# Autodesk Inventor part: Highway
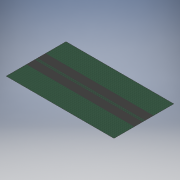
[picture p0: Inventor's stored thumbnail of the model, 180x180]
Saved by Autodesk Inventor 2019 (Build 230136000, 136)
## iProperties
Created: 2018-12
Part Number: Highway
Material: Generic
Document SubType Name: Modeling
Designer: Patel Family
Density: 1 g/cm^3
Appearance: Green Polished
Author: Patel Family
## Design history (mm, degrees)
sketch "Sketch1"
  geometry: L1 (-1703.23, 945.159)-(1703.23, 945.159); L2 (1703.23, 945.159)-(1703.23, -945.159); L3 (1703.23, -945.159)-(-1703.23, -945.159); L4 (-1703.23, -945.159)-(-1703.23, 945.159); L5 (-1703.23, 945.159)-(1703.23, -945.159); L6 (1703.23, 945.159)-(-1703.23, -945.159); 1 further point
  constraints: 12 end point, 2 midpoint, 2 parallel, 1 horizontal, 1 perpendicular
  dimensions: "d8" = 1890.31814 distance between parallel lines of L1 L3
extrude "Extrusion1" new body sketch "Sketch1" distance "d0" = 0.2; taper "d1" = 0 deg
sketch "Sketch2"
  geometry: L1 (1703.23, -945.159)-(1703.23, 945.159) reference; L2 (-1703.23, -44.963)-(1703.23, -44.963); L3 (1703.23, -44.963)-(1703.23, 44.963); L4 (1703.23, 44.963)-(-1703.23, 44.963); L5 (-1703.23, 44.963)-(-1703.23, -44.963); L6 (-1703.23, -44.963)-(1703.23, 44.963); L7 (1703.23, -44.963)-(-1703.23, 44.963); L8 (1703.23, -44.963)-(-1703.23, -44.963); L9 (-1703.23, -44.963)-(-1703.23, 44.963); L10 (-1703.23, 44.963)-(1703.23, 44.963); L11 (1703.23, 44.963)-(1703.23, -44.963); L12 (1703.23, -44.963)-(-1703.23, 44.963); L13 (-1703.23, -44.963)-(1703.23, 44.963); 1 further point
  constraints: 24 end point, 4 midpoint, 4 parallel, 2 horizontal, 2 perpendicular, 1 point on line
  dimensions: "d9" = 89.92631 distance between parallel lines of L2 L4
extrude "Extrusion2" join sketch "Sketch2" distance "d2" = 0.0002; taper "d3" = 0 deg
sketch "Sketch3"
  geometry: L1 (-1705.81, -296.952)-(1705.81, -296.952); L2 (1705.81, -296.952)-(1705.81, 296.952); L3 (1705.81, 296.952)-(-1705.81, 296.952); L4 (-1705.81, 296.952)-(-1705.81, -296.952); L5 (-1705.81, -296.952)-(1705.81, 296.952); L6 (1705.81, -296.952)-(-1705.81, 296.952); 1 further point
  constraints: 12 end point, 2 midpoint, 2 parallel, 1 horizontal, 1 perpendicular
  dimensions: "d10" = 593.9047 distance between parallel lines of L1 L3
extrude "Extrusion3" cut sketch "Sketch3" distance "d4" = 0.0004; taper "d5" = 0 deg
sketch "Sketch4"
  geometry: L1 (1703.23, 296.952)-(1703.23, -296.952) reference; L2 (-1703.23, -3.684)-(1703.23, -3.684); L3 (1703.23, -3.684)-(1703.23, 3.684); L4 (1703.23, 3.684)-(-1703.23, 3.684); L5 (-1703.23, 3.684)-(-1703.23, -3.684); L6 (-1703.23, -3.684)-(1703.23, 3.684); L7 (1703.23, -3.684)-(-1703.23, 3.684); 1 further point
  constraints: 12 end point, 2 midpoint, 2 parallel, 1 horizontal, 1 perpendicular, 1 point on line
extrude "Extrusion4" join sketch "Sketch4" distance "d6" = 0.0002; taper "d7" = 0 deg
sketch "Sketch5"
  geometry: L1 (-1703.23, -945.159)-(-1703.23, 945.159) reference; L2 (1703.23, -42.63)-(-1703.23, -42.63); L3 (-1703.23, -42.63)-(-1703.23, 42.63); L4 (-1703.23, 42.63)-(1703.23, 42.63); L5 (1703.23, 42.63)-(1703.23, -42.63); L6 (1703.23, -42.63)-(-1703.23, 42.63); L7 (-1703.23, -42.63)-(1703.23, 42.63); 1 further point
  constraints: 12 end point, 2 midpoint, 2 parallel, 1 horizontal, 1 perpendicular, 1 point on line
extrude "Extrusion5" join sketch "Sketch5" distance "d11" = 0.00001; taper "d12" = 0 deg
body "Solid1"
